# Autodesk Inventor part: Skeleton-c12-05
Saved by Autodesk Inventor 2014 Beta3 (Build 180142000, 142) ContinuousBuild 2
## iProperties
Created: 2011-01
Part Number: Skeleton-c12-05
Material: Generic
Document SubType Name: Modeling
Designer: Thom Tremblay
Density: 1 g/cm^3
Appearance: Generic
_SkeletonDoc: Frame Skeleton File
_Version: 15.0.0
Author: Thom Tremblay
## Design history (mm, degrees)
sketch "Reference Skeleton"
  geometry: L1 through (404.523, 1164.395) direction (1, 0); L2 through (325.691, 1070.446) direction (1, 0); 34 other entities
  constraints: 10 horizontal
